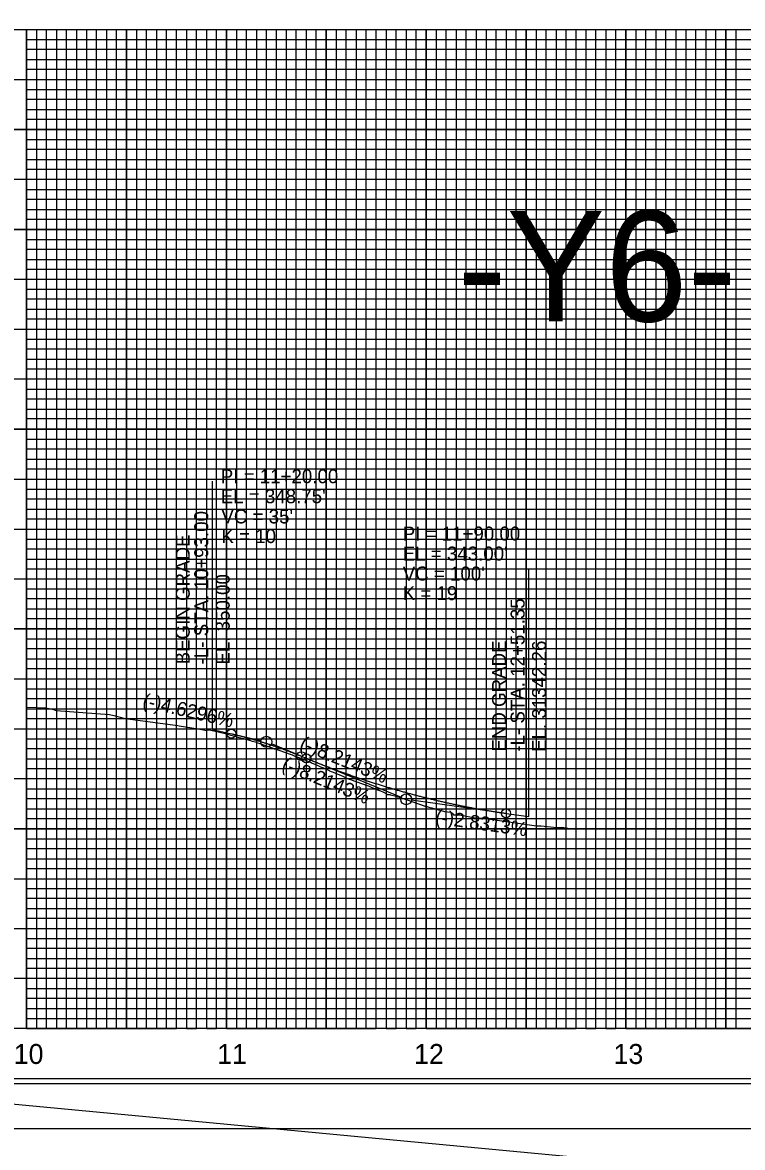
# Model space of a CAD drawing. Extents: x 571503 to 593215, y -77195 to -51828.
# Drawn here: x 588100 to 588461, y -53762 to -53198 of the extents above; entities that cross this region are included whole.
import ezdxf

# ---------------------------------------------------------------- set-up
doc = ezdxf.new("R2010")
doc.units = 0
for name, color, linetype in [('Default', 7, 'Continuous'), ('Exist Vertical Profile Ground Line', 7, 'Continuous'), ('Exist Vertical Profile Horizontal Axis Label Major', 7, 'Continuous'), ('Prop PFL Text', 7, 'Continuous'), ('Prop Vertical Profile Curve Label', 7, 'Continuous'), ('Prop Vertical Profile Grade', 7, 'Continuous'), ('Prop Vertical Profile Grade Label', 7, 'Continuous'), ('Prop VPI Label', 7, 'Continuous'), ('Sheet Clip Boundary CELL', 7, 'Continuous'), ('Sheet DOT Grid CELL', 7, 'Continuous'), ('Sheet Plot Border Inside CELL', 7, 'Continuous'), ('Sheet Plot Border Outside CELL', 7, 'Continuous'), ('Sheet Profile CELL', 7, 'Continuous'), ('Sheet Profile Grid Major CELL', 7, 'Continuous'), ('Sheet Profile Grid Middle CELL', 7, 'Continuous'), ('Sheet Profile Grid Minor CELL', 7, 'Continuous')]:
    doc.layers.add(name, color=color, linetype=linetype)

msp = doc.modelspace()

# ---------------------------------------------------------------- linework, layer by layer
at = {"layer": 'Default'}
msp.add_line((588102.46, -53701.95), (588052.46, -53701.95), dxfattribs=at)
at = {"layer": 'Exist Vertical Profile Ground Line'}
for points in [[(588102.46, -53541.1), (588102.52, -53541.1), (588111.92, -53541.5), (588114.54, -53541.93), (588115.93, -53542.34), (588117.34, -53542.71), (588143.99, -53544.76), (588146.16, -53545.3), (588151.72, -53546.81), (588178.17, -53550.26), (588178.87, -53550.45), (588188.38, -53551.89), (588190.93, -53552.43), (588191.6, -53552.58), (588192.61, -53552.83), (588192.97, -53552.51), (588193.66, -53552.49), (588193.94, -53552.53), (588195.41, -53552.84), (588196.84, -53553.15), (588198.27, -53553.47), (588199.69, -53553.8), (588201.12, -53554.15), (588202.55, -53554.51), (588203.97, -53554.88), (588205.31, -53555.24), (588205.4, -53555.26), (588206.83, -53555.67), (588207.76, -53555.94), (588208.26, -53556.07), (588209.68, -53556.45), (588211.11, -53556.84), (588212.54, -53557.23), (588212.61, -53557.26), (588213.96, -53557.65), (588215.39, -53558.09), (588216.82, -53558.53), (588218.24, -53558.99), (588219.67, -53559.47), (588221.1, -53559.95), (588222.53, -53560.45), (588223.95, -53560.96), (588225.38, -53561.48), (588226.08, -53561.74), (588226.37, -53561.9), (588226.64, -53561.95), (588226.68, -53561.95), (588226.81, -53561.99), (588228.23, -53562.47), (588229.66, -53562.97), (588231.09, -53563.47), (588232.51, -53563.99), (588233.94, -53564.51), (588235.37, -53565.04), (588236.8, -53565.59), (588238.22, -53566.14), (588239.65, -53566.71), (588241.08, -53567.29), (588242.5, -53567.87), (588243.93, -53568.47), (588244.89, -53568.88), (588245.36, -53569.07), (588246.78, -53569.67), (588248.21, -53570.27), (588249.64, -53570.89), (588251.07, -53571.52), (588252.49, -53572.16), (588253.92, -53572.81), (588254.12, -53572.9), (588254.93, -53573.24), (588255.35, -53573.41), (588256.77, -53573.99), (588258.2, -53574.59), (588259.63, -53575.2), (588261.05, -53575.82), (588262.48, -53576.46), (588262.83, -53576.62), (588263.91, -53577.19), (588263.95, -53577.21), (588264.51, -53577.33), (588264.66, -53577.36), (588265.34, -53577.59), (588266.76, -53578.08), (588268.19, -53578.58), (588269.62, -53579.09), (588271.04, -53579.62), (588272.47, -53580.16), (588273.9, -53580.71), (588275.33, -53581.27), (588276.75, -53581.85), (588278.18, -53582.43), (588279.61, -53583.03), (588281.03, -53583.64), (588281.45, -53583.82), (588282.46, -53584.4), (588283.04, -53584.76), (588283.89, -53584.84), (588284.25, -53584.89), (588284.66, -53584.96), (588285.31, -53585.14), (588286.74, -53585.55)], [(588286.74, -53585.55), (588288.17, -53585.97), (588289.6, -53586.4), (588291.02, -53586.85), (588292.45, -53587.3), (588293.88, -53587.77), (588295.3, -53588.25), (588296.73, -53588.74), (588298.16, -53589.24), (588299.58, -53589.75), (588301.01, -53590.28), (588301.41, -53590.43), (588301.74, -53590.59), (588302, -53590.64), (588302.24, -53590.69), (588302.44, -53590.74), (588303.87, -53591.13), (588305.29, -53591.52), (588309.82, -53592.81), (588311.1, -53593.2), (588311.68, -53593.3), (588314.65, -53593.74), (588314.93, -53593.87), (588315.28, -53593.99), (588315.61, -53594.36), (588316.13, -53594.92), (588316.69, -53595.01), (588317.09, -53595), (588318.32, -53594.95), (588319.18, -53595.03), (588326.91, -53596.49), (588328.44, -53596.59), (588331.14, -53596.71), (588357.67, -53600.56), (588359.97, -53600.43), (588367.77, -53601.27), (588370.4, -53601.25), (588374.32, -53601.78)]]:
    msp.add_lwpolyline(points, dxfattribs=at)
at = {"layer": 'Prop PFL Text'}
msp.add_line((571620.66, -52186.29), (592499.52, -54154.87), dxfattribs=at)
at = {"layer": 'Prop Vertical Profile Curve Label'}
for centre in [(588204.96, -53554.4), (588239.96, -53565.63), (588242.46, -53566.66), (588342.46, -53594.27)]:
    msp.add_circle(centre, 2.25, dxfattribs=at)
at = {"layer": 'Prop Vertical Profile Grade'}
for p, q in [((588195.46, -53552.2), (588204.96, -53554.4)), ((588239.96, -53565.63), (588242.46, -53566.66)), ((588342.46, -53594.27), (588353.81, -53595.88))]:
    msp.add_line(p, q, dxfattribs=at)
for points in [[(588204.96, -53554.4), (588205.66, -53554.56), (588206.36, -53554.72), (588207.06, -53554.89), (588207.76, -53555.06), (588208.46, -53555.24), (588209.16, -53555.41), (588209.86, -53555.59), (588210.56, -53555.77), (588211.26, -53555.96), (588211.96, -53556.14), (588212.66, -53556.33), (588213.36, -53556.52), (588214.06, -53556.71), (588214.76, -53556.91), (588215.46, -53557.11), (588216.16, -53557.31), (588216.86, -53557.51), (588217.56, -53557.72), (588218.26, -53557.93), (588218.96, -53558.14), (588219.66, -53558.35), (588220.36, -53558.57), (588221.06, -53558.79), (588221.76, -53559.01), (588222.46, -53559.23), (588223.16, -53559.46), (588223.86, -53559.69), (588224.56, -53559.92), (588225.26, -53560.15), (588225.96, -53560.39), (588226.66, -53560.62), (588227.36, -53560.87), (588228.06, -53561.11), (588228.76, -53561.36), (588229.46, -53561.6), (588230.16, -53561.85), (588230.86, -53562.11), (588231.56, -53562.36), (588232.26, -53562.62), (588232.96, -53562.88), (588233.66, -53563.15), (588234.36, -53563.41), (588235.06, -53563.68), (588235.76, -53563.95), (588236.46, -53564.23), (588237.16, -53564.5), (588237.86, -53564.78), (588238.56, -53565.06), (588239.26, -53565.35), (588239.96, -53565.63)], [(588242.46, -53566.66), (588244.46, -53567.48), (588246.46, -53568.28), (588248.46, -53569.08), (588250.46, -53569.86), (588252.46, -53570.63), (588254.46, -53571.4), (588256.46, -53572.15), (588258.46, -53572.89), (588260.46, -53573.62), (588262.46, -53574.34), (588264.46, -53575.05), (588266.46, -53575.74), (588268.46, -53576.43), (588270.46, -53577.11), (588272.46, -53577.77), (588274.46, -53578.43), (588276.46, -53579.07), (588278.46, -53579.7), (588280.46, -53580.32), (588282.46, -53580.94), (588284.46, -53581.54), (588286.46, -53582.13), (588288.46, -53582.71), (588290.46, -53583.27), (588292.46, -53583.83), (588294.46, -53584.38), (588296.46, -53584.92), (588298.46, -53585.44), (588300.46, -53585.96), (588302.46, -53586.46), (588304.46, -53586.95), (588306.46, -53587.43), (588308.46, -53587.91), (588310.46, -53588.37), (588312.46, -53588.82), (588314.46, -53589.26), (588316.46, -53589.68), (588318.46, -53590.1), (588320.46, -53590.51), (588322.46, -53590.91), (588324.46, -53591.29), (588326.46, -53591.67), (588328.46, -53592.03), (588330.46, -53592.38), (588332.46, -53592.72), (588334.46, -53593.06), (588336.46, -53593.38), (588338.46, -53593.69), (588340.46, -53593.99), (588342.46, -53594.27)]]:
    msp.add_spline(points, degree=3, dxfattribs=at)
at = {"layer": 'Prop VPI Label'}
for p, q in [((588195.46, -53552.2), (588195.46, -53428.06)), ((588353.81, -53595.88), (588353.81, -53471.75)), ((588204.96, -53554.4), (588219.78, -53557.83)), ((588239.96, -53565.63), (588225, -53559.49)), ((588242.46, -53566.66), (588289.92, -53586.15)), ((588342.46, -53594.27), (588295.18, -53587.58))]:
    msp.add_line(p, q, dxfattribs=at)
for centre in [(588222.46, -53558.45), (588292.46, -53587.2)]:
    msp.add_circle(centre, 2.75, dxfattribs=at)
at = {"layer": 'Sheet Clip Boundary CELL'}
msp.add_lwpolyline([(588102.46, -53201.95), (589502.46, -53201.95), (589502.46, -53701.95), (588102.46, -53701.95)], close=True, dxfattribs=at)
at = {"layer": 'Sheet DOT Grid CELL'}
for p, q in [((588052.46, -53201.95), (589552.35, -53201.95)), ((588102.46, -53701.95), (588102.46, -53201.95)), ((588102.46, -53201.95), (588102.46, -53701.95)), ((588152.46, -53701.95), (588152.46, -53201.95)), ((588152.46, -53201.95), (588152.46, -53701.95)), ((588202.46, -53701.95), (588202.46, -53201.95)), ((588202.46, -53201.95), (588202.46, -53701.95)), ((588252.46, -53701.95), (588252.46, -53201.95)), ((588252.46, -53201.95), (588252.46, -53701.95)), ((588302.46, -53701.95), (588302.46, -53201.95)), ((588302.46, -53201.95), (588302.46, -53701.95)), ((588352.46, -53701.95), (588352.46, -53201.95)), ((588352.46, -53201.95), (588352.46, -53701.95)), ((588402.46, -53701.95), (588402.46, -53201.95)), ((588402.46, -53201.95), (588402.46, -53701.95)), ((588452.46, -53701.95), (588452.46, -53201.95)), ((588452.46, -53201.95), (588452.46, -53701.95)), ((588052.46, -53251.95), (589552.46, -53251.95)), ((588052.46, -53251.95), (589552.35, -53251.95)), ((588052.46, -53301.95), (589552.46, -53301.95)), ((588052.46, -53301.95), (589552.35, -53301.95)), ((588052.46, -53351.95), (589552.46, -53351.95)), ((588052.46, -53351.95), (589552.35, -53351.95)), ((588052.46, -53401.95), (589552.46, -53401.95)), ((588052.46, -53401.95), (589552.35, -53401.95)), ((588052.46, -53451.95), (589552.46, -53451.95)), ((588052.46, -53451.95), (589552.35, -53451.95)), ((588052.46, -53501.95), (589552.46, -53501.95)), ((588052.46, -53501.95), (589552.35, -53501.95)), ((588052.46, -53551.95), (589552.46, -53551.95)), ((588052.46, -53551.95), (589552.35, -53551.95)), ((588052.46, -53601.95), (589552.46, -53601.95)), ((588052.46, -53601.95), (589552.35, -53601.95)), ((588052.46, -53651.95), (589552.46, -53651.95)), ((588052.46, -53651.95), (589552.35, -53651.95))]:
    msp.add_line(p, q, dxfattribs=at)
at = {"layer": 'Sheet Plot Border Inside CELL'}
msp.add_lwpolyline([(587898.46, -53729.5), (589564.96, -53729.5), (589564.96, -52674.4), (587898.46, -52674.4)], close=True, dxfattribs=at)
at = {"layer": 'Sheet Plot Border Outside CELL'}
msp.add_lwpolyline([(587885.46, -53751.95), (589569.46, -53751.95), (589569.46, -52651.95), (587885.46, -52651.95)], close=True, dxfattribs=at)
at = {"layer": 'Sheet Profile CELL'}
for p, q in [((588052.46, -53201.95), (589552.46, -53201.95)), ((589552.46, -53701.95), (588052.46, -53701.95)), ((588052.46, -53726.95), (589552.46, -53726.95)), ((587885.46, -53751.95), (589569.46, -53751.95))]:
    msp.add_line(p, q, dxfattribs=at)
msp.add_lwpolyline([(589552.46, -52676.95), (588052.46, -52676.95), (588052.46, -53726.95), (589552.46, -53726.95)], close=True, dxfattribs=at)
at = {"layer": 'Sheet Profile Grid Major CELL'}
for points in [[(588102.46, -53201.95), (588102.46, -53701.95), (588152.46, -53701.95), (588152.46, -53201.95), (588202.46, -53201.95), (588202.46, -53701.95), (588252.46, -53701.95), (588252.46, -53201.95), (588302.46, -53201.95), (588302.46, -53701.95), (588352.46, -53701.95), (588352.46, -53201.95), (588402.46, -53201.95), (588402.46, -53701.95), (588452.46, -53701.95), (588452.46, -53201.95), (588502.46, -53201.95)], [(589552.46, -53251.95), (588052.46, -53251.95)], [(589552.46, -53301.95), (588052.46, -53301.95), (588052.46, -53351.95), (589552.46, -53351.95)], [(589552.46, -53401.95), (588052.46, -53401.95), (588052.46, -53451.95), (589552.46, -53451.95)], [(589552.46, -53501.95), (588052.46, -53501.95), (588052.46, -53551.95), (589552.46, -53551.95)], [(589552.46, -53601.95), (588052.46, -53601.95), (588052.46, -53601.95), (588052.46, -53651.95), (589552.46, -53651.95)], [(589552.46, -53701.95), (588052.46, -53701.95)]]:
    msp.add_lwpolyline(points, dxfattribs=at)
at = {"layer": 'Sheet Profile Grid Middle CELL'}
for points in [[(588077.46, -53201.95), (588127.46, -53201.95), (588127.46, -53701.95), (588177.46, -53701.95), (588177.46, -53201.95), (588227.46, -53201.95), (588227.46, -53701.95), (588277.46, -53701.95), (588277.46, -53201.95), (588327.46, -53201.95), (588327.46, -53701.95), (588377.46, -53701.95), (588377.46, -53201.95), (588427.46, -53201.95), (588427.46, -53701.95), (588477.46, -53701.95)], [(588052.46, -53226.95), (589552.46, -53226.95)], [(589552.46, -53276.95), (588052.46, -53276.95), (588052.46, -53326.95), (589552.46, -53326.95)], [(589552.46, -53376.95), (588052.46, -53376.95), (588052.46, -53426.95), (589552.46, -53426.95)], [(589552.46, -53476.95), (588052.46, -53476.95), (588052.46, -53526.95), (589552.46, -53526.95)], [(589552.46, -53576.95), (588052.46, -53576.95), (588052.46, -53626.95), (589552.46, -53626.95)], [(589552.46, -53676.95), (588052.46, -53676.95)]]:
    msp.add_lwpolyline(points, dxfattribs=at)
at = {"layer": 'Sheet Profile Grid Minor CELL'}
for p, q in [((588102.46, -53206.95), (589502.46, -53206.95)), ((589502.46, -53211.95), (588102.46, -53211.95)), ((588102.46, -53216.95), (589502.46, -53216.95)), ((589502.46, -53221.95), (588102.46, -53221.95)), ((588102.46, -53231.95), (589502.46, -53231.95)), ((589502.46, -53236.95), (588102.46, -53236.95)), ((588102.46, -53241.95), (589502.46, -53241.95)), ((589502.46, -53246.95), (588102.46, -53246.95)), ((588102.46, -53256.95), (589502.46, -53256.95)), ((589502.46, -53261.95), (588102.46, -53261.95)), ((588102.46, -53266.95), (589502.46, -53266.95)), ((589502.46, -53271.95), (588102.46, -53271.95)), ((588102.46, -53281.95), (589502.46, -53281.95)), ((589502.46, -53286.95), (588102.46, -53286.95)), ((588102.46, -53291.95), (589502.46, -53291.95)), ((589502.46, -53296.95), (588102.46, -53296.95)), ((588102.46, -53306.95), (589502.46, -53306.95)), ((589502.46, -53311.95), (588102.46, -53311.95)), ((588102.46, -53316.95), (589502.46, -53316.95)), ((589502.46, -53321.95), (588102.46, -53321.95)), ((588102.46, -53331.95), (589502.46, -53331.95)), ((589502.46, -53336.95), (588102.46, -53336.95)), ((588102.46, -53341.95), (589502.46, -53341.95)), ((589502.46, -53346.95), (588102.46, -53346.95)), ((588102.46, -53356.95), (589502.46, -53356.95)), ((589502.46, -53361.95), (588102.46, -53361.95)), ((588102.46, -53366.95), (589502.46, -53366.95)), ((589502.46, -53371.95), (588102.46, -53371.95)), ((588102.46, -53381.95), (589502.46, -53381.95)), ((589502.46, -53386.95), (588102.46, -53386.95)), ((588102.46, -53391.95), (589502.46, -53391.95)), ((589502.46, -53396.95), (588102.46, -53396.8)), ((588102.46, -53406.95), (589502.46, -53406.95)), ((589502.46, -53411.95), (588102.46, -53411.95)), ((588102.46, -53416.95), (589502.46, -53416.95)), ((589502.46, -53421.95), (588102.46, -53421.95)), ((588102.46, -53431.95), (589502.46, -53431.95)), ((589502.46, -53436.95), (588102.46, -53436.95)), ((588102.46, -53441.95), (589502.46, -53441.95)), ((589502.46, -53446.95), (588102.46, -53446.95)), ((588102.46, -53456.95), (589502.46, -53456.95)), ((589502.46, -53461.95), (588102.46, -53461.95)), ((588102.46, -53466.95), (589502.46, -53466.95)), ((589502.46, -53471.95), (588102.46, -53471.95)), ((588102.46, -53481.95), (589502.46, -53481.95)), ((589502.46, -53486.95), (588102.46, -53486.95)), ((588102.46, -53491.95), (589502.46, -53491.95)), ((589502.46, -53496.95), (588102.46, -53496.95)), ((588102.46, -53506.95), (589502.46, -53506.95)), ((589502.46, -53511.95), (588102.46, -53511.95)), ((588102.46, -53516.95), (589502.46, -53516.95)), ((589502.46, -53521.95), (588102.46, -53521.95)), ((588102.46, -53531.95), (589502.46, -53531.95)), ((589502.46, -53536.95), (588102.46, -53536.95)), ((588102.46, -53541.95), (589502.46, -53541.95)), ((589502.46, -53546.95), (588102.46, -53546.95)), ((588102.46, -53556.95), (589502.46, -53556.95)), ((589502.46, -53561.95), (588102.46, -53561.95)), ((588102.46, -53566.95), (589502.46, -53566.95)), ((589502.46, -53571.95), (588102.46, -53571.95)), ((588102.46, -53581.95), (589502.46, -53581.95)), ((589502.46, -53586.95), (588102.46, -53586.95)), ((588102.46, -53591.95), (589502.46, -53591.95)), ((589502.46, -53596.95), (588102.46, -53596.95)), ((588102.46, -53606.95), (589502.46, -53606.95)), ((589502.46, -53611.95), (588102.46, -53611.95)), ((588102.46, -53616.95), (589502.46, -53616.95)), ((589502.46, -53621.95), (588102.46, -53621.95)), ((588102.46, -53631.95), (589502.46, -53631.95)), ((589502.46, -53636.95), (588102.46, -53636.95)), ((588102.46, -53641.95), (589502.46, -53641.95)), ((589502.46, -53646.95), (588102.46, -53646.95)), ((588102.46, -53656.95), (589502.46, -53656.95)), ((589502.46, -53661.95), (588102.46, -53661.95)), ((588102.46, -53666.95), (589502.46, -53666.95)), ((589502.46, -53671.95), (588102.46, -53671.95)), ((588102.46, -53681.95), (589502.46, -53681.95)), ((589502.46, -53686.95), (588102.46, -53686.95)), ((588102.46, -53691.95), (589502.46, -53691.95)), ((588102.46, -53696.95), (589502.46, -53696.95))]:
    msp.add_line(p, q, dxfattribs=at)
for points in [[(588102.46, -53201.95), (588107.46, -53201.95), (588107.46, -53701.95), (588112.46, -53701.95), (588112.46, -53201.95), (588117.46, -53201.95), (588117.46, -53701.95), (588122.46, -53701.95), (588122.46, -53201.95), (588132.46, -53201.95), (588132.46, -53701.95), (588137.46, -53701.95), (588137.46, -53201.95), (588142.46, -53201.95), (588142.46, -53701.95), (588147.46, -53701.95), (588157.46, -53701.95), (588162.46, -53701.95), (588162.46, -53201.95), (588167.46, -53201.95), (588167.46, -53701.95), (588172.46, -53701.95), (588172.46, -53201.95), (588182.46, -53201.95), (588182.46, -53701.95), (588187.46, -53701.95), (588187.46, -53201.95), (588192.46, -53201.95), (588192.46, -53701.95), (588197.46, -53701.95), (588197.46, -53201.95), (588207.46, -53201.95), (588207.46, -53701.95), (588212.46, -53701.95), (588212.46, -53201.95), (588217.46, -53201.95), (588217.46, -53701.95), (588222.46, -53701.95), (588222.46, -53201.95), (588232.46, -53201.95), (588232.46, -53701.95), (588237.46, -53701.95), (588237.46, -53201.95), (588242.46, -53201.95), (588242.46, -53701.95), (588247.46, -53701.95), (588247.46, -53201.95), (588257.46, -53201.95), (588257.46, -53701.95), (588262.46, -53701.95), (588262.46, -53201.95), (588267.46, -53201.95), (588267.46, -53701.95), (588272.46, -53701.95), (588272.46, -53201.95), (588282.46, -53201.95), (588282.46, -53701.95), (588287.46, -53701.95), (588287.46, -53201.95), (588292.46, -53201.95), (588292.46, -53701.95), (588297.46, -53701.95), (588297.46, -53201.95), (588307.46, -53201.95), (588307.46, -53701.95), (588312.46, -53701.95), (588312.46, -53201.95), (588317.46, -53201.95), (588317.46, -53701.95)], [(588147.46, -53701.95), (588147.46, -53201.95), (588157.46, -53201.95), (588157.46, -53701.95)], [(588317.46, -53701.95), (588322.46, -53701.95), (588322.46, -53201.95), (588332.46, -53201.95), (588332.46, -53701.95), (588337.46, -53701.95), (588337.46, -53201.95), (588342.46, -53201.95), (588342.46, -53701.95), (588347.46, -53701.95), (588347.46, -53201.95), (588357.46, -53201.95), (588357.46, -53701.95), (588362.46, -53701.95), (588362.46, -53201.95), (588367.46, -53201.95), (588367.46, -53701.95), (588372.46, -53701.95), (588372.46, -53201.95), (588382.46, -53201.95), (588382.46, -53701.95), (588387.46, -53701.95), (588387.46, -53201.95), (588392.46, -53201.95), (588392.46, -53701.95), (588397.46, -53701.95), (588397.46, -53201.95), (588407.46, -53201.95), (588407.46, -53701.95), (588412.46, -53701.95), (588412.46, -53201.95), (588417.46, -53201.95), (588417.46, -53701.95), (588422.46, -53701.95), (588422.46, -53201.95), (588432.46, -53201.95), (588432.46, -53701.95), (588437.46, -53701.95), (588437.46, -53201.95), (588442.46, -53201.95), (588442.46, -53701.95), (588447.46, -53701.95), (588447.46, -53201.95), (588457.46, -53201.95), (588457.46, -53701.95), (588462.46, -53701.95)]]:
    msp.add_lwpolyline(points, dxfattribs=at)

# ---------------------------------------------------------------- texts
at = {"layer": 'Default'}
msp.add_text('-Y6-', height=55.361, dxfattribs=at).set_placement((588318.03, -53348.05))
at = {"layer": 'Exist Vertical Profile Horizontal Axis Label Major'}
for s, p in [('10', (588096.04, -53719.7)), ('11', (588197.88, -53719.7)), ('12', (588296.43, -53719.7)), ('13', (588396.27, -53719.7))]:
    msp.add_text(s, height=10, dxfattribs=at).set_placement(p)
at = {"layer": 'Prop Vertical Profile Curve Label'}
for s, p in [("VC = 35'", (588199.96, -53449.13)), ('K = 10', (588199.96, -53458.96)), ("VC = 100'", (588290.73, -53477.71)), ('K = 19', (588290.73, -53487.54))]:
    msp.add_text(s, height=7, dxfattribs=at).set_placement(p)
at = {"layer": 'Prop Vertical Profile Grade Label'}
for s, rotation, p in [('(-)4.6296%', 346.9666, (588160.06, -53540.92)), ('(-)8.2143%', 337.6713, (588238.58, -53561.82)), ('(-)8.2143%', 337.6713, (588229.64, -53572.21)), ('(-)2.8313%', 351.9425, (588306.71, -53599.31))]:
    msp.add_text(s, height=7, rotation=rotation, dxfattribs=at).set_placement(p)
at = {"layer": 'Prop VPI Label'}
for s, p in [('PI = 11+20.00', (588199.64, -53429.02)), ("EL = 348.75'", (588199.64, -53439.02)), ('PI = 11+90.00', (588290.73, -53457.71)), ("EL = 343.00'", (588290.73, -53467.71))]:
    msp.add_text(s, height=7, dxfattribs=at).set_placement(p)
for s, p in [('-L- STA. 10+93.00', (588193.39, -53519.67)), ('BEGIN GRADE', (588184.1, -53519.67)), ('EL. 350.00', (588204.12, -53519.81)), ('-L- STA. 12+51.35', (588351.74, -53563.36)), ('END GRADE', (588342.45, -53563.36)), ('EL. 31342.26', (588362.47, -53563.49))]:
    msp.add_text(s, height=7, rotation=90, dxfattribs=at).set_placement(p)

doc.saveas('drawing.dxf')
